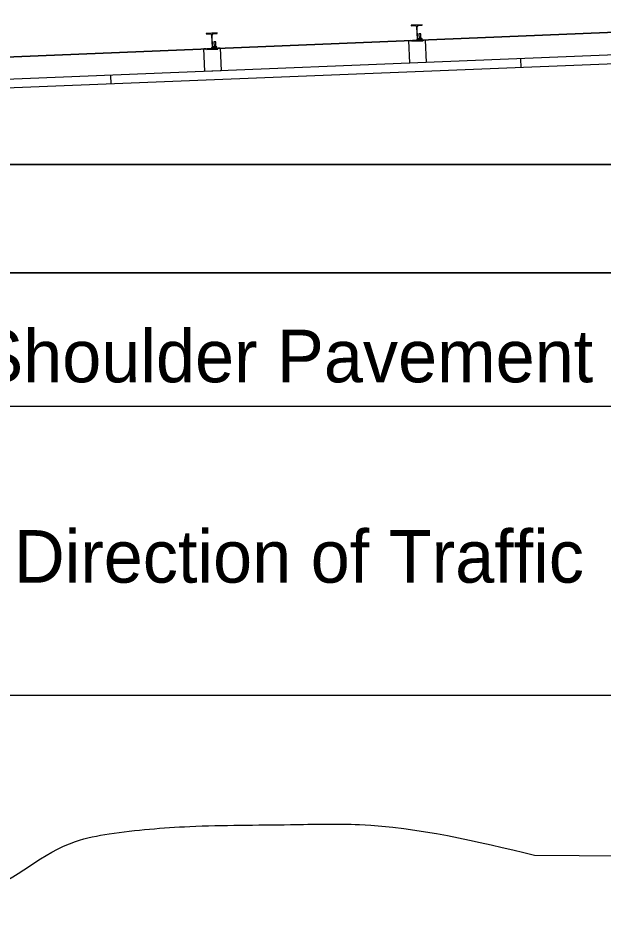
# Model space of a CAD drawing. Extents: x 10038 to 81668, y 7924 to 11018.
# Drawn here: x 11212.1 to 11390.3, y 9469.8 to 9742.6 of the extents above; entities that cross this region are included whole.
import ezdxf

# ---------------------------------------------------------------- set-up
doc = ezdxf.new("R2010")
doc.units = 0
for name, color, linetype in [('DsnShtMinorGrid07', 7, 'Continuous'), ('DsnShtMinorGrid10', 7, 'Continuous'), ('DsnShtMinorGrid11', 7, 'Continuous'), ('Level 60', 7, 'Continuous')]:
    doc.layers.add(name, color=color, linetype=linetype)

msp = doc.modelspace()

# ---------------------------------------------------------------- linework, layer by layer
at = {"layer": 'DsnShtMinorGrid07'}
for p, q in [((11335.24, 9740.5), (11331.91, 9740.37)), ((11335.24, 9740.5), (11331.91, 9740.37)), ((11331.91, 9740.37), (11331.92, 9740.21)), ((11331.91, 9740.37), (11331.92, 9740.21)), ((11331.92, 9740.21), (11333.09, 9740.26)), ((11331.92, 9740.21), (11333.09, 9740.26)), ((11333.52, 9739.86), (11333.67, 9736.11)), ((11333.52, 9739.86), (11333.67, 9736.11)), ((11333.83, 9736.12), (11333.68, 9739.87)), ((11333.83, 9736.12), (11333.68, 9739.87)), ((11334.08, 9740.3), (11335.25, 9740.35)), ((11334.08, 9740.3), (11335.25, 9740.35)), ((11335.25, 9740.35), (11335.24, 9740.5)), ((11335.25, 9740.35), (11335.24, 9740.5)), ((11272.79, 9738), (11269.46, 9737.87)), ((11272.79, 9738), (11269.46, 9737.87)), ((11269.46, 9737.87), (11269.47, 9737.71)), ((11269.46, 9737.87), (11269.47, 9737.71)), ((11269.47, 9737.71), (11270.64, 9737.76)), ((11269.47, 9737.71), (11270.64, 9737.76)), ((11271.07, 9737.36), (11271.22, 9733.61)), ((11271.07, 9737.36), (11271.22, 9733.61)), ((11271.38, 9733.62), (11271.23, 9737.37)), ((11271.38, 9733.62), (11271.23, 9737.37)), ((11271.63, 9737.8), (11272.8, 9737.85)), ((11271.63, 9737.8), (11272.8, 9737.85)), ((11272.8, 9737.85), (11272.79, 9738)), ((11272.8, 9737.85), (11272.79, 9738)), ((11334.78, 9737.77), (11334.26, 9737.75)), ((11334.78, 9737.77), (11334.26, 9737.75)), ((11334.26, 9737.75), (11334.32, 9736.24)), ((11334.26, 9737.75), (11334.32, 9736.24)), ((11334.84, 9736.26), (11334.78, 9737.77)), ((11334.84, 9736.26), (11334.78, 9737.77)), ((11272.33, 9735.27), (11271.81, 9735.25)), ((11272.33, 9735.27), (11271.81, 9735.25)), ((11271.81, 9735.25), (11271.87, 9733.74)), ((11271.81, 9735.25), (11271.87, 9733.74)), ((11272.39, 9733.76), (11272.33, 9735.27)), ((11272.39, 9733.76), (11272.33, 9735.27)), ((11331.16, 9735.75), (11331.78, 9735.78)), ((11331.43, 9728.79), (11331.16, 9735.75)), ((11331.79, 9735.46), (11331.78, 9735.78)), ((11335.54, 9735.61), (11331.79, 9735.46)), ((11333.27, 9735.68), (11332.1, 9735.63)), ((11333.27, 9735.68), (11332.1, 9735.63)), ((11332.1, 9735.63), (11332.1, 9735.48)), ((11332.1, 9735.63), (11332.1, 9735.48)), ((11332.1, 9735.48), (11335.44, 9735.61)), ((11332.1, 9735.48), (11335.44, 9735.61)), ((11334.06, 9736.23), (11333.98, 9736.18)), ((11334.06, 9736.23), (11333.98, 9736.18)), ((11333.98, 9736.18), (11333.99, 9735.8)), ((11333.99, 9735.8), (11333.98, 9736.18)), ((11335.02, 9736.27), (11334.06, 9736.23)), ((11334.06, 9736.23), (11335.02, 9736.27)), ((11335.43, 9735.77), (11334.26, 9735.72)), ((11335.43, 9735.77), (11334.26, 9735.72)), ((11334.28, 9736.19), (11334.29, 9735.77)), ((11334.29, 9735.77), (11334.28, 9736.19)), ((11334.29, 9735.77), (11334.28, 9736.19)), ((11334.32, 9736.24), (11334.84, 9736.26)), ((11334.89, 9735.8), (11334.88, 9736.21)), ((11334.88, 9736.21), (11334.89, 9735.8)), ((11334.89, 9735.8), (11334.88, 9736.21)), ((11335.09, 9736.27), (11335.02, 9736.27)), ((11335.02, 9736.27), (11335.09, 9736.27)), ((11335.18, 9736.22), (11335.09, 9736.27)), ((11335.18, 9736.22), (11335.09, 9736.27)), ((11335.11, 9735.75), (11335.2, 9735.81)), ((11335.11, 9735.75), (11335.2, 9735.81)), ((11335.2, 9735.81), (11335.18, 9736.22)), ((11335.2, 9735.81), (11335.18, 9736.22)), ((11335.44, 9735.61), (11335.43, 9735.77)), ((11335.44, 9735.61), (11335.43, 9735.77)), ((11335.53, 9735.93), (11336.15, 9735.95)), ((11335.53, 9735.93), (11335.54, 9735.61)), ((11336.15, 9735.95), (11336.43, 9728.99)), ((11268.71, 9733.25), (11269.33, 9733.28)), ((11268.98, 9726.3), (11268.71, 9733.25)), ((11269.34, 9732.97), (11269.33, 9733.28)), ((11273.09, 9733.12), (11269.34, 9732.97)), ((11270.82, 9733.18), (11269.65, 9733.13)), ((11270.82, 9733.18), (11269.65, 9733.13)), ((11269.65, 9733.13), (11269.65, 9732.98)), ((11269.65, 9733.13), (11269.65, 9732.98)), ((11269.65, 9732.98), (11272.99, 9733.11)), ((11269.65, 9732.98), (11272.99, 9733.11)), ((11271.61, 9733.73), (11271.53, 9733.68)), ((11271.61, 9733.73), (11271.53, 9733.68)), ((11271.53, 9733.68), (11271.54, 9733.3)), ((11271.54, 9733.3), (11271.53, 9733.68)), ((11272.57, 9733.77), (11271.61, 9733.73)), ((11271.61, 9733.73), (11272.57, 9733.77)), ((11272.98, 9733.27), (11271.81, 9733.22)), ((11272.98, 9733.27), (11271.81, 9733.22)), ((11271.83, 9733.69), (11271.84, 9733.27)), ((11271.84, 9733.27), (11271.83, 9733.69)), ((11271.84, 9733.27), (11271.83, 9733.69)), ((11271.87, 9733.74), (11272.39, 9733.76)), ((11272.45, 9733.3), (11272.43, 9733.71)), ((11272.43, 9733.71), (11272.45, 9733.3)), ((11272.45, 9733.3), (11272.43, 9733.71)), ((11272.64, 9733.78), (11272.57, 9733.77)), ((11272.57, 9733.77), (11272.64, 9733.78)), ((11272.73, 9733.73), (11272.64, 9733.78)), ((11272.73, 9733.73), (11272.64, 9733.78)), ((11272.66, 9733.25), (11272.75, 9733.31)), ((11272.66, 9733.25), (11272.75, 9733.31)), ((11272.75, 9733.31), (11272.73, 9733.73)), ((11272.75, 9733.31), (11272.73, 9733.73)), ((11272.99, 9733.11), (11272.98, 9733.27)), ((11272.99, 9733.11), (11272.98, 9733.27)), ((11273.08, 9733.43), (11273.7, 9733.45)), ((11273.08, 9733.43), (11273.09, 9733.12)), ((11273.7, 9733.45), (11273.98, 9726.5)), ((11273.98, 9726.5), (11268.98, 9726.3))]:
    msp.add_line(p, q, dxfattribs=at)
for points in [[(11333.99, 9735.8), (11333.99, 9735.8)], [(11334.26, 9735.72), (11335.11, 9735.75), (11335.11, 9735.75)], [(11271.54, 9733.3), (11271.54, 9733.3)], [(11271.81, 9733.22), (11272.66, 9733.25), (11272.66, 9733.25)]]:
    msp.add_lwpolyline(points, dxfattribs=at)
for centre, start, end in [((11333.1, 9739.84), 2.2841, 92.2932), ((11333.1, 9739.84), 2.2841, 92.2932), ((11334.09, 9739.88), 92.2981, 182.2871), ((11334.09, 9739.88), 92.2981, 182.2871), ((11270.65, 9737.34), 2.2841, 92.2932), ((11270.65, 9737.34), 2.2841, 92.2932), ((11271.64, 9737.38), 92.2981, 182.2871), ((11271.64, 9737.38), 92.2981, 182.2871), ((11333.25, 9736.1), 272.2981, 2.2871), ((11333.25, 9736.1), 272.2981, 2.2871), ((11334.24, 9736.13), 182.2841, 272.2932), ((11334.24, 9736.13), 182.2841, 272.2932), ((11334.24, 9736.13), 233.1773, 272.2932), ((11270.8, 9733.6), 272.2981, 2.2871), ((11270.8, 9733.6), 272.2981, 2.2871), ((11271.79, 9733.64), 182.2841, 272.2932), ((11271.79, 9733.64), 182.2841, 272.2932), ((11271.79, 9733.64), 233.1773, 272.2932)]:
    msp.add_arc(centre, 0.417, start, end, dxfattribs=at)
for points in [[(11334.28, 9736.19), (11334.25, 9736.2), (11334.2, 9736.23), (11334.12, 9736.24), (11334.04, 9736.22), (11334, 9736.19), (11333.98, 9736.18)], [(11333.98, 9736.18), (11334, 9736.19), (11334.04, 9736.22), (11334.12, 9736.24), (11334.2, 9736.23), (11334.25, 9736.2), (11334.28, 9736.19)], [(11334.28, 9736.19), (11334.25, 9736.2), (11334.2, 9736.23), (11334.12, 9736.24), (11334.04, 9736.22), (11334, 9736.19), (11333.98, 9736.18)], [(11334.2, 9735.73), (11334.21, 9735.73), (11334.24, 9735.74), (11334.27, 9735.76), (11334.29, 9735.77)], [(11334.88, 9736.21), (11334.83, 9736.22), (11334.72, 9736.25), (11334.56, 9736.25), (11334.41, 9736.23), (11334.32, 9736.2), (11334.28, 9736.19)], [(11334.28, 9736.19), (11334.32, 9736.2), (11334.41, 9736.23), (11334.56, 9736.25), (11334.72, 9736.25), (11334.83, 9736.22), (11334.88, 9736.21)], [(11334.88, 9736.21), (11334.83, 9736.22), (11334.72, 9736.25), (11334.56, 9736.25), (11334.41, 9736.23), (11334.32, 9736.2), (11334.28, 9736.19)], [(11334.29, 9735.77), (11334.35, 9735.76), (11334.45, 9735.73), (11334.61, 9735.73), (11334.76, 9735.75), (11334.85, 9735.78), (11334.89, 9735.8)], [(11334.89, 9735.8), (11334.85, 9735.78), (11334.76, 9735.75), (11334.61, 9735.73), (11334.45, 9735.73), (11334.35, 9735.76), (11334.29, 9735.77)], [(11334.29, 9735.77), (11334.35, 9735.76), (11334.45, 9735.73), (11334.61, 9735.73), (11334.76, 9735.75), (11334.85, 9735.78), (11334.89, 9735.8)], [(11335.18, 9736.22), (11335.16, 9736.23), (11335.13, 9736.25), (11335.06, 9736.27), (11334.99, 9736.27), (11334.93, 9736.24), (11334.89, 9736.22), (11334.88, 9736.21)], [(11334.88, 9736.21), (11334.89, 9736.22), (11334.93, 9736.24), (11334.99, 9736.27), (11335.06, 9736.27), (11335.13, 9736.25), (11335.16, 9736.23), (11335.18, 9736.22)], [(11335.18, 9736.22), (11335.16, 9736.23), (11335.13, 9736.25), (11335.06, 9736.27), (11334.99, 9736.27), (11334.93, 9736.24), (11334.89, 9736.22), (11334.88, 9736.21)], [(11334.89, 9735.8), (11334.91, 9735.79), (11334.94, 9735.77), (11335.01, 9735.75), (11335.08, 9735.75), (11335.15, 9735.78), (11335.18, 9735.8), (11335.2, 9735.81)], [(11335.2, 9735.81), (11335.18, 9735.8), (11335.15, 9735.78), (11335.08, 9735.75), (11335.01, 9735.75), (11334.94, 9735.77), (11334.91, 9735.79), (11334.89, 9735.8)], [(11334.89, 9735.8), (11334.91, 9735.79), (11334.94, 9735.77), (11335.01, 9735.75), (11335.08, 9735.75), (11335.15, 9735.78), (11335.18, 9735.8), (11335.2, 9735.81)], [(11271.83, 9733.69), (11271.8, 9733.7), (11271.75, 9733.73), (11271.67, 9733.74), (11271.59, 9733.72), (11271.55, 9733.69), (11271.53, 9733.68)], [(11271.53, 9733.68), (11271.55, 9733.69), (11271.59, 9733.72), (11271.67, 9733.74), (11271.75, 9733.73), (11271.8, 9733.7), (11271.83, 9733.69)], [(11271.83, 9733.69), (11271.8, 9733.7), (11271.75, 9733.73), (11271.67, 9733.74), (11271.59, 9733.72), (11271.55, 9733.69), (11271.53, 9733.68)], [(11271.75, 9733.23), (11271.76, 9733.23), (11271.79, 9733.24), (11271.82, 9733.26), (11271.84, 9733.27)], [(11272.43, 9733.71), (11272.38, 9733.73), (11272.27, 9733.75), (11272.11, 9733.76), (11271.96, 9733.73), (11271.87, 9733.7), (11271.83, 9733.69)], [(11271.83, 9733.69), (11271.87, 9733.7), (11271.96, 9733.73), (11272.11, 9733.76), (11272.27, 9733.75), (11272.38, 9733.73), (11272.43, 9733.71)], [(11272.43, 9733.71), (11272.38, 9733.73), (11272.27, 9733.75), (11272.11, 9733.76), (11271.96, 9733.73), (11271.87, 9733.7), (11271.83, 9733.69)], [(11271.84, 9733.27), (11271.9, 9733.26), (11272, 9733.24), (11272.16, 9733.23), (11272.31, 9733.25), (11272.4, 9733.28), (11272.45, 9733.3)], [(11272.45, 9733.3), (11272.4, 9733.28), (11272.31, 9733.25), (11272.16, 9733.23), (11272, 9733.24), (11271.9, 9733.26), (11271.84, 9733.27)], [(11271.84, 9733.27), (11271.9, 9733.26), (11272, 9733.24), (11272.16, 9733.23), (11272.31, 9733.25), (11272.4, 9733.28), (11272.45, 9733.3)], [(11272.73, 9733.73), (11272.71, 9733.74), (11272.68, 9733.75), (11272.61, 9733.77), (11272.54, 9733.77), (11272.48, 9733.74), (11272.44, 9733.72), (11272.43, 9733.71)], [(11272.43, 9733.71), (11272.44, 9733.72), (11272.48, 9733.74), (11272.54, 9733.77), (11272.61, 9733.77), (11272.68, 9733.75), (11272.71, 9733.74), (11272.73, 9733.73)], [(11272.73, 9733.73), (11272.71, 9733.74), (11272.68, 9733.75), (11272.61, 9733.77), (11272.54, 9733.77), (11272.48, 9733.74), (11272.44, 9733.72), (11272.43, 9733.71)], [(11272.45, 9733.3), (11272.46, 9733.29), (11272.49, 9733.27), (11272.56, 9733.25), (11272.63, 9733.25), (11272.7, 9733.28), (11272.73, 9733.3), (11272.75, 9733.31)], [(11272.75, 9733.31), (11272.73, 9733.3), (11272.7, 9733.28), (11272.63, 9733.25), (11272.56, 9733.25), (11272.49, 9733.27), (11272.46, 9733.29), (11272.45, 9733.3)], [(11272.45, 9733.3), (11272.46, 9733.29), (11272.49, 9733.27), (11272.56, 9733.25), (11272.63, 9733.25), (11272.7, 9733.28), (11272.73, 9733.3), (11272.75, 9733.31)]]:
    msp.add_open_spline(points, degree=3, dxfattribs=at)
at = {"layer": 'DsnShtMinorGrid11'}
for p, q in [((11452.36, 9740.67), (11023.5, 9723.06)), ((10524.54, 9697.98), (11498.9, 9697.98)), ((11556.45, 9697.98), (10524.54, 9697.98)), ((10350.4, 9536.44), (11992.44, 9536.44))]:
    msp.add_line(p, q, dxfattribs=at)
at = {"layer": 'Level 60'}
for p, q in [((11023.5, 9723.06), (11498.9, 9742.58)), ((11335.24, 9740.5), (11331.91, 9740.37)), ((11331.91, 9740.37), (11331.92, 9740.21)), ((11331.92, 9740.21), (11333.09, 9740.26)), ((11333.52, 9739.86), (11333.67, 9736.11)), ((11333.83, 9736.12), (11333.68, 9739.87)), ((11334.08, 9740.3), (11335.25, 9740.35)), ((11335.25, 9740.35), (11335.24, 9740.5)), ((11272.79, 9738), (11269.46, 9737.87)), ((11269.46, 9737.87), (11269.47, 9737.71)), ((11269.47, 9737.71), (11270.64, 9737.76)), ((11271.07, 9737.36), (11271.22, 9733.61)), ((11271.38, 9733.62), (11271.23, 9737.37)), ((11271.63, 9737.8), (11272.8, 9737.85)), ((11272.8, 9737.85), (11272.79, 9738)), ((11334.78, 9737.77), (11334.26, 9737.75)), ((11334.26, 9737.75), (11334.32, 9736.24)), ((11334.84, 9736.26), (11334.78, 9737.77)), ((11272.33, 9735.27), (11271.81, 9735.25)), ((11271.81, 9735.25), (11271.87, 9733.74)), ((11272.39, 9733.76), (11272.33, 9735.27)), ((11331.16, 9735.75), (11331.78, 9735.78)), ((11331.43, 9728.79), (11331.16, 9735.75)), ((11331.79, 9735.46), (11331.78, 9735.78)), ((11335.54, 9735.61), (11331.79, 9735.46)), ((11333.27, 9735.68), (11332.1, 9735.63)), ((11332.1, 9735.63), (11332.1, 9735.48)), ((11332.1, 9735.48), (11335.44, 9735.61)), ((11334.06, 9736.23), (11333.98, 9736.18)), ((11333.99, 9735.8), (11333.98, 9736.18)), ((11334.06, 9736.23), (11335.02, 9736.27)), ((11335.43, 9735.77), (11334.26, 9735.72)), ((11334.29, 9735.77), (11334.28, 9736.19)), ((11334.89, 9735.8), (11334.88, 9736.21)), ((11335.02, 9736.27), (11335.09, 9736.27)), ((11335.18, 9736.22), (11335.09, 9736.27)), ((11335.11, 9735.75), (11335.2, 9735.81)), ((11335.2, 9735.81), (11335.18, 9736.22)), ((11335.44, 9735.61), (11335.43, 9735.77)), ((11335.53, 9735.93), (11336.15, 9735.95)), ((11335.53, 9735.93), (11335.54, 9735.61)), ((11336.15, 9735.95), (11336.43, 9728.99)), ((11402.1, 9731.62), (10990.54, 9715.16)), ((11268.71, 9733.25), (11269.33, 9733.28)), ((11268.98, 9726.3), (11268.71, 9733.25)), ((11269.34, 9732.97), (11269.33, 9733.28)), ((11273.09, 9733.12), (11269.34, 9732.97)), ((11270.82, 9733.18), (11269.65, 9733.13)), ((11269.65, 9733.13), (11269.65, 9732.98)), ((11269.65, 9732.98), (11272.99, 9733.11)), ((11271.61, 9733.73), (11271.53, 9733.68)), ((11271.54, 9733.3), (11271.53, 9733.68)), ((11271.61, 9733.73), (11272.57, 9733.77)), ((11272.98, 9733.27), (11271.81, 9733.22)), ((11271.84, 9733.27), (11271.83, 9733.69)), ((11272.45, 9733.3), (11272.43, 9733.71)), ((11272.57, 9733.77), (11272.64, 9733.78)), ((11272.73, 9733.73), (11272.64, 9733.78)), ((11272.66, 9733.25), (11272.75, 9733.31)), ((11272.75, 9733.31), (11272.73, 9733.73)), ((11272.99, 9733.11), (11272.98, 9733.27)), ((11273.08, 9733.43), (11273.7, 9733.45)), ((11273.08, 9733.43), (11273.09, 9733.12)), ((11273.7, 9733.45), (11273.98, 9726.5)), ((11402.21, 9728.92), (10990.54, 9712.45)), ((11336.43, 9728.99), (11331.43, 9728.79)), ((11365.16, 9730.14), (11365.26, 9727.44)), ((11273.98, 9726.5), (11268.98, 9726.3)), ((11240.26, 9725.15), (11240.36, 9722.44)), ((10366.79, 9697.98), (11498.9, 9697.98)), ((10345.8, 9665), (11993.27, 9665)), ((11498.9, 9665), (10345.8, 9665)), ((10367.01, 9624.35), (11980.8, 9624.35)), ((11369.49, 9487.72), (11698.69, 9485.27))]:
    msp.add_line(p, q, dxfattribs=at)
for centre, start, end in [((11333.1, 9739.84), 2.2841, 92.2932), ((11334.09, 9739.88), 92.2981, 182.2871), ((11270.65, 9737.34), 2.2841, 92.2932), ((11271.64, 9737.38), 92.2981, 182.2871), ((11333.25, 9736.1), 272.2981, 2.2871), ((11334.24, 9736.13), 182.2841, 272.2932), ((11270.8, 9733.6), 272.2981, 2.2871), ((11271.79, 9733.64), 182.2841, 272.2932)]:
    msp.add_arc(centre, 0.417, start, end, dxfattribs=at)
for points in [[(11334.28, 9736.19), (11334.25, 9736.2), (11334.2, 9736.23), (11334.12, 9736.24), (11334.04, 9736.22), (11334, 9736.19), (11333.98, 9736.18)], [(11334.2, 9735.73), (11334.21, 9735.73), (11334.24, 9735.74), (11334.27, 9735.76), (11334.29, 9735.77)], [(11334.88, 9736.21), (11334.83, 9736.22), (11334.72, 9736.25), (11334.56, 9736.25), (11334.41, 9736.23), (11334.32, 9736.2), (11334.28, 9736.19)], [(11334.29, 9735.77), (11334.35, 9735.76), (11334.45, 9735.73), (11334.61, 9735.73), (11334.76, 9735.75), (11334.85, 9735.78), (11334.89, 9735.8)], [(11335.18, 9736.22), (11335.16, 9736.23), (11335.13, 9736.25), (11335.06, 9736.27), (11334.99, 9736.27), (11334.93, 9736.24), (11334.89, 9736.22), (11334.88, 9736.21)], [(11334.89, 9735.8), (11334.91, 9735.79), (11334.94, 9735.77), (11335.01, 9735.75), (11335.08, 9735.75), (11335.15, 9735.78), (11335.18, 9735.8), (11335.2, 9735.81)], [(11271.83, 9733.69), (11271.8, 9733.7), (11271.75, 9733.73), (11271.67, 9733.74), (11271.59, 9733.72), (11271.55, 9733.69), (11271.53, 9733.68)], [(11271.75, 9733.23), (11271.76, 9733.23), (11271.79, 9733.24), (11271.82, 9733.26), (11271.84, 9733.27)], [(11272.43, 9733.71), (11272.38, 9733.73), (11272.27, 9733.75), (11272.11, 9733.76), (11271.96, 9733.73), (11271.87, 9733.7), (11271.83, 9733.69)], [(11271.84, 9733.27), (11271.9, 9733.26), (11272, 9733.24), (11272.16, 9733.23), (11272.31, 9733.25), (11272.4, 9733.28), (11272.45, 9733.3)], [(11272.73, 9733.73), (11272.71, 9733.74), (11272.68, 9733.75), (11272.61, 9733.77), (11272.54, 9733.77), (11272.48, 9733.74), (11272.44, 9733.72), (11272.43, 9733.71)], [(11272.45, 9733.3), (11272.46, 9733.29), (11272.49, 9733.27), (11272.56, 9733.25), (11272.63, 9733.25), (11272.7, 9733.28), (11272.73, 9733.3), (11272.75, 9733.31)]]:
    msp.add_open_spline(points, degree=3, dxfattribs=at)
msp.add_spline([(10371.08, 9480.63), (10380.51, 9483.21), (10410.73, 9482.64), (10438.67, 9474.65), (10466.04, 9473.51), (10484.29, 9479.22), (10511.09, 9478.65), (10535.61, 9474.08), (10559.56, 9477.51), (10576.66, 9482.64), (10616.58, 9475.22), (10643.38, 9471.23), (10667.9, 9480.36), (10690.71, 9482.07), (10729.49, 9476.36), (10728.92, 9476.36), (10750.07, 9474.76), (10787.14, 9477.61), (10812.23, 9480.47), (10831.04, 9483.89), (10854.99, 9483.32), (10876.66, 9479.9), (10902.32, 9475.33), (10935.97, 9476.47), (10967.33, 9482.75), (10992.42, 9482.75), (11024.35, 9475.33), (11053.43, 9472.48), (11087.08, 9479.33), (11119.58, 9482.75), (11153.79, 9475.9), (11179.45, 9473.05), (11201.69, 9476.47), (11229.63, 9491.88), (11239.9, 9494.16), (11264.42, 9496.44), (11295.08, 9497.01), (11316.18, 9497.01), (11369.49, 9487.72)], degree=3, dxfattribs=at)

# ---------------------------------------------------------------- texts
at = {"layer": 'DsnShtMinorGrid10'}
for s, p in [('Edge of Shoulder Pavement', (11119.72, 9631.65)), ('Direction of Traffic', (11210.91, 9570.65))]:
    msp.add_text(s, height=16, dxfattribs=at).set_placement(p)

doc.saveas('drawing.dxf')
